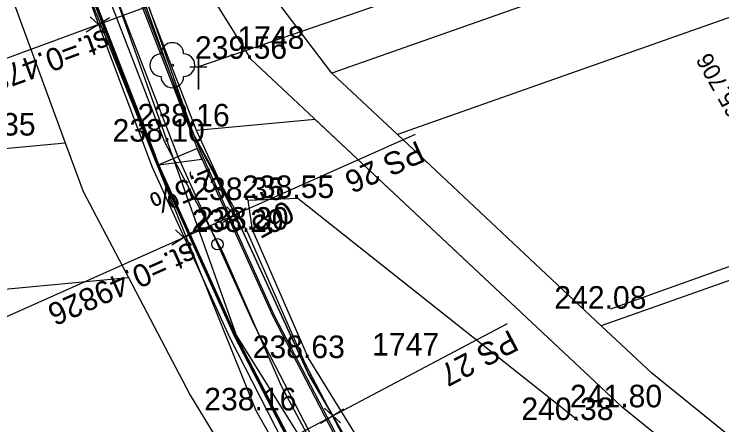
# Model space of a CAD drawing. Extents: x -601754 to -601440, y -1201912 to -1200862.
# Drawn here: x -601565.6 to -601502.8, y -1201341.8 to -1201305.3 of the extents above; entities that cross this region are included whole.
import ezdxf

# ---------------------------------------------------------------- set-up
doc = ezdxf.new("R2010")
doc.units = 0
for name, color, linetype in [('Hranice parcel', 7, 'Continuous'), ('Parcelní čísla', 7, 'Continuous'), ('u_drén', 7, 'Continuous'), ('u_hrany', 7, 'Continuous'), ('u_krizky', 7, 'Continuous'), ('u_návrh', 7, 'Continuous'), ('u_oblouky', 7, 'Continuous'), ('u_osa', 7, 'Continuous'), ('u_popis', 7, 'Continuous'), ('u_pricne_cesta', 7, 'Continuous'), ('u_S0 02', 7, 'Continuous'), ('u_sklony', 7, 'Continuous'), ('u_staniceni', 7, 'Continuous'), ('u_strom', 7, 'Continuous'), ('u_terénní úpravy', 7, 'Continuous'), ('u_vyska', 7, 'Continuous')]:
    doc.layers.add(name, color=color, linetype=linetype)

msp = doc.modelspace()

# ---------------------------------------------------------------- linework, layer by layer
at = {"layer": 'Hranice parcel'}
for p, q in [((-601454.585, -1201288.829), (-601531.62, -1201316.01)), ((-601531.62, -1201316.01), (-601537.44, -1201310.56)), ((-601454.585, -1201312.111), (-601513.53, -1201332.97)), ((-601513.53, -1201332.97), (-601531.62, -1201316.01)), ((-601716.54, -1201331.34), (-601561.09, -1201316.74)), ((-601718.96, -1201344.02), (-601555.49, -1201328.67))]:
    msp.add_line(p, q, dxfattribs=at)
for points in [[(-601587.88, -1201265.89), (-601565.6, -1201304.49), (-601561.09, -1201316.74)], [(-601549.44, -1201315.65), (-601555, -1201301.25), (-601559.75, -1201287.64), (-601564.51, -1201274), (-601567.94, -1201267.13)], [(-601454.585, -1201281.403), (-601537.44, -1201310.56)], [(-601537.44, -1201310.56), (-601543.06, -1201303.13), (-601546.8, -1201296.02)], [(-601508.86, -1201342.47), (-601511.66, -1201340.2), (-601538.92, -1201314.66), (-601549.44, -1201315.65)], [(-601531.84, -1201350.34), (-601539.52, -1201337.25), (-601549.44, -1201315.65)], [(-601561.09, -1201316.74), (-601559.5, -1201321.05), (-601555.49, -1201328.67)], [(-601555.49, -1201328.67), (-601550, -1201339.12), (-601542.3, -1201351.82)], [(-601500.94, -1201343.73), (-601509.03, -1201337.18), (-601513.53, -1201332.97)]]:
    msp.add_lwpolyline(points, dxfattribs=at)
at = {"layer": 'u_drén'}
for points in [[(-601567.079, -1201280.135), (-601558.833, -1201303.296), (-601553.194, -1201317.864)], [(-601553.194, -1201317.864), (-601552.875, -1201318.687), (-601546.074, -1201333.752), (-601538.46, -1201348.424), (-601530.069, -1201362.635), (-601525.78, -1201369.465), (-601523.226, -1201373.891), (-601521.024, -1201378.462), (-601519.169, -1201383.184), (-601517.66, -1201388.066), (-601516.532, -1201392.263), (-601515.324, -1201397.601), (-601514.551, -1201402.98), (-601514.21, -1201408.403), (-601514.303, -1201413.875), (-601516.032, -1201444.23), (-601516.195, -1201450.215), (-601516.005, -1201456.227), (-601515.463, -1201462.19), (-601510.248, -1201505.371), (-601509.825, -1201509.657), (-601509.591, -1201513.936), (-601509.544, -1201518.242), (-601509.788, -1201540.615)]]:
    msp.add_lwpolyline(points, dxfattribs=at)
at = {"layer": 'u_hrany'}
for p, q in [((-601549.28, -1201311.99), (-601549.28, -1201308.99)), ((-601550.03, -1201309.99), (-601548.53, -1201309.99))]:
    msp.add_line(p, q, dxfattribs=at)
for points in [[(-601564.55, -1201274.22), (-601554.98, -1201301.75), (-601550.1, -1201315.28), (-601544.95, -1201324.64), (-601539.81, -1201336.34), (-601533.54, -1201348.31)], [(-601563.6, -1201276.76), (-601556.83, -1201286.65), (-601558.4, -1201287.18), (-601544.66, -1201309.28)], [(-601541.87, -1201338.39), (-601547.11, -1201326.43), (-601552.28, -1201316.63), (-601557.82, -1201302.28), (-601562.06, -1201289.84)], [(-601563.01, -1201293.69), (-601544.18, -1201340.47), (-601528.42, -1201368.16), (-601520.9, -1201374.92)], [(-601544.66, -1201309.28), (-601511.66, -1201340.2)], [(-601544.47, -1201324.44), (-601544.87, -1201321.81), (-601540.45, -1201321.63), (-601515.6, -1201341.33)], [(-601512.68, -1201331.45), (-601485.16, -1201321.6)], [(-601528.36, -1201353.88), (-601539.51, -1201335.83), (-601544.47, -1201324.44)], [(-601520.9, -1201374.92), (-601531.36, -1201358), (-601541.87, -1201338.39)]]:
    msp.add_lwpolyline(points, dxfattribs=at)
at = {"layer": 'u_krizky'}
for p, q in [((-601557.178, -1201305.642), (-601559.231, -1201306.922)), ((-601557.471, -1201306.869), (-601558.898, -1201305.549)), ((-601545.041, -1201322.519), (-601547.094, -1201323.799)), ((-601545.335, -1201323.745), (-601546.761, -1201322.426)), ((-601549.886, -1201325.774), (-601551.312, -1201324.455)), ((-601549.593, -1201324.548), (-601551.646, -1201325.828)), ((-601536.377, -1201340.355), (-601538.43, -1201341.635)), ((-601536.671, -1201341.582), (-601538.097, -1201340.262))]:
    msp.add_line(p, q, dxfattribs=at)
at = {"layer": 'u_návrh'}
for points in [[(-601563.683, -1201278.418), (-601555.294, -1201301.982), (-601549.753, -1201316.295)], [(-601563.542, -1201278.368), (-601555.153, -1201301.929), (-601549.253, -1201317.17), (-601542.541, -1201332.04), (-601535.025, -1201346.521), (-601526.716, -1201360.593), (-601522.417, -1201367.44), (-601519.753, -1201372.056), (-601517.425, -1201376.89), (-601515.462, -1201381.885), (-601513.889, -1201386.977), (-601512.721, -1201391.321), (-601511.461, -1201396.888), (-601510.644, -1201402.577), (-601510.283, -1201408.313), (-601510.38, -1201414.02), (-601512.11, -1201444.395)], [(-601567.28, -1201279.795), (-601558.903, -1201303.323), (-601552.944, -1201318.716), (-601546.141, -1201333.785), (-601538.525, -1201348.46), (-601530.133, -1201362.674), (-601525.844, -1201369.504), (-601523.292, -1201373.926), (-601521.093, -1201378.492), (-601519.24, -1201383.209), (-601517.732, -1201388.087), (-601516.605, -1201392.281), (-601515.398, -1201397.615), (-601514.626, -1201402.988), (-601514.285, -1201408.405), (-601514.378, -1201413.873), (-601516.107, -1201444.227)], [(-601567.139, -1201279.745), (-601558.763, -1201303.27), (-601553.125, -1201317.832)], [(-601549.753, -1201316.295), (-601549.392, -1201317.228), (-601542.676, -1201332.105), (-601535.157, -1201346.594), (-601526.844, -1201360.671), (-601522.546, -1201367.518), (-601519.886, -1201372.126), (-601517.562, -1201376.951), (-601515.604, -1201381.935), (-601514.033, -1201387.018), (-601512.867, -1201391.357), (-601511.609, -1201396.915), (-601510.793, -1201402.592), (-601510.433, -1201408.317), (-601510.53, -1201414.015), (-601512.26, -1201444.389), (-601512.419, -1201450.207), (-601512.236, -1201455.996), (-601511.709, -1201461.793), (-601506.495, -1201504.959), (-601506.06, -1201509.368), (-601505.817, -1201513.812), (-601505.769, -1201518.242), (-601506.187, -1201556.503)], [(-601553.136, -1201317.803), (-601552.806, -1201318.658), (-601546.006, -1201333.72), (-601538.394, -1201348.388), (-601530.005, -1201362.596), (-601525.716, -1201369.427), (-601523.16, -1201373.856), (-601520.956, -1201378.432), (-601519.098, -1201383.159), (-601517.588, -1201388.045), (-601516.46, -1201392.245), (-601515.25, -1201397.587), (-601514.477, -1201402.972), (-601514.135, -1201408.402), (-601514.228, -1201413.878), (-601515.957, -1201444.233), (-601516.12, -1201450.215), (-601515.93, -1201456.223), (-601515.388, -1201462.182), (-601510.174, -1201505.363), (-601509.75, -1201509.651), (-601509.516, -1201513.934), (-601509.469, -1201518.242), (-601509.714, -1201540.624)]]:
    msp.add_lwpolyline(points, dxfattribs=at)
at = {"layer": 'u_oblouky'}
for p in [(-601557.028, -1201302.626), (-601528.425, -1201361.634)]:
    msp.add_line(p, (-601545.965, -1201333.7), dxfattribs=at)
at = {"layer": 'u_osa'}
msp.add_lwpolyline([(-601557.028, -1201302.626), (-601551.099, -1201317.943), (-601544.341, -1201332.912), (-601536.775, -1201347.491), (-601528.425, -1201361.634), (-601524.131, -1201368.472), (-601521.523, -1201372.991), (-601519.259, -1201377.691), (-601517.351, -1201382.547), (-601515.811, -1201387.532), (-601514.663, -1201391.801), (-601513.43, -1201397.251), (-601512.635, -1201402.782), (-601512.284, -1201408.359), (-601512.379, -1201413.946), (-601514.108, -1201444.311)], dxfattribs=at)
at = {"layer": 'u_popis'}
msp.add_lwpolyline([(-601523.837, -1201245.04), (-601523.837, -1201301.24), (-601549.28, -1201309.99)], dxfattribs=at)
at = {"layer": 'u_pricne_cesta'}
for points in [[(-601537.167, -1201298.539), (-601555.941, -1201305.435), (-601574.714, -1201312.332)], [(-601530.032, -1201316), (-601548.3, -1201324.143), (-601566.567, -1201332.287)], [(-601521.874, -1201332.787), (-601539.559, -1201342.128), (-601557.243, -1201351.468)]]:
    msp.add_lwpolyline(points, dxfattribs=at)
at = {"layer": 'u_S0 02'}
for p, q in [((-601549.28, -1201308.99), (-601549.28, -1201311.99)), ((-601550.03, -1201309.99), (-601548.53, -1201309.99))]:
    msp.add_line(p, q, dxfattribs=at)
at = {"layer": 'u_sklony'}
msp.add_lwpolyline([(-601549.392, -1201317.228), (-601552.787, -1201318.698), (-601548.962, -1201318.179)], close=True, dxfattribs=at)
at = {"layer": 'u_staniceni'}
msp.add_circle((-601547.584, -1201325.729), 0.5, dxfattribs=at)
at = {"layer": 'u_strom'}
msp.add_circle((-601551.59, -1201309.85), 0.1, dxfattribs=at)
for centre, start, end in [((-601551.59, -1201308.85), 0, 180), ((-601552.59, -1201309.85), 90, 270), ((-601550.59, -1201309.85), 270, 90), ((-601551.59, -1201310.85), 180, 0)]:
    msp.add_arc(centre, 1, start, end, dxfattribs=at)
at = {"layer": 'u_terénní úpravy'}
for points in [[(-601563.549, -1201276.755), (-601560.467, -1201285.585), (-601555.466, -1201299.915), (-601555, -1201301.25), (-601553.702, -1201304.613), (-601549.711, -1201315.986), (-601546.008, -1201323.122), (-601539.52, -1201337.25), (-601537.344, -1201340.958), (-601533.54, -1201348.31), (-601527.44, -1201357.911), (-601522.351, -1201366.758), (-601519.36, -1201371.808), (-601517.434, -1201375.343), (-601516.299, -1201378.722), (-601515.181, -1201381.785), (-601513.502, -1201386.766), (-601512.274, -1201391.071), (-601511.36, -1201394.458), (-601510.891, -1201396.937), (-601510.105, -1201401.304), (-601509.884, -1201408.41), (-601509.865, -1201414.917), (-601511.161, -1201434.926)], [(-601565.037, -1201287.212), (-601558.145, -1201306.245), (-601553.368, -1201318.894), (-601550.549, -1201325.146), (-601546.519, -1201333.968), (-601541.758, -1201343.289), (-601538.578, -1201348.49), (-601532.041, -1201360.744), (-601526.088, -1201369.629), (-601523.664, -1201374.122), (-601522.125, -1201377.501), (-601519.788, -1201383.401), (-601518.29, -1201388.248), (-601517.27, -1201392.04), (-601516.455, -1201395.572), (-601515.96, -1201398.024), (-601515.065, -1201403.029), (-601514.933, -1201414.628), (-601514.933, -1201414.628), (-601516.331, -1201434.631)]]:
    msp.add_lwpolyline(points, dxfattribs=at)

# ---------------------------------------------------------------- texts
at = {"layer": 'Parcelní čísla'}
for s, p in [('1748', (-601545.819, -1201308.396)), ('1747', (-601533.858, -1201335.606))]:
    msp.add_text(s, height=2, dxfattribs=at).set_placement(p)
at = {"layer": 'u_oblouky'}
msp.add_text('L=65.706', height=1.5, rotation=119.44653, dxfattribs=at).set_placement((-601499.737, -1201315.948))
at = {"layer": 'u_pricne_cesta'}
for s, rotation, p in [('st.=0.47805', 200.17178, (-601557.55, -1201306.589)), ('PS 26', 204.02677, (-601529.818, -1201316.482)), ('st.=0.49826', 204.02677, (-601550, -1201325.479)), ('PS 27', 207.84151, (-601521.627, -1201333.254))]:
    msp.add_text(s, height=2, rotation=rotation, dxfattribs=at).set_placement(p)
at = {"layer": 'u_sklony'}
msp.add_text('2,5%', height=2, rotation=203.41655, dxfattribs=at).set_placement((-601548.183, -1201318.931))
at = {"layer": 'u_staniceni'}
msp.add_text('0.5', height=2, rotation=209.03181, dxfattribs=at).set_placement((-601541.526, -1201321.762))
at = {"layer": 'u_vyska'}
for s, p in [('239.56', (-601549.586, -1201309.28)), ('238.16', (-601554.68, -1201315.28)), ('235.35', (-601571.906, -1201316.09)), ('238.10', (-601556.896, -1201316.63)), ('238.35', (-601549.826, -1201321.81)), ('238.55', (-601545.406, -1201321.63)), ('238.30', (-601549.457, -1201324.44)), ('238.29', (-601549.882, -1201324.64)), ('242.08', (-601517.695, -1201331.45)), ('238.63', (-601544.461, -1201335.83)), ('241.80', (-601516.304, -1201340.2)), ('238.16', (-601548.76, -1201340.47)), ('240.38', (-601520.615, -1201341.33))]:
    msp.add_text(s, height=2, dxfattribs=at).set_placement(p)

doc.saveas('drawing.dxf')
